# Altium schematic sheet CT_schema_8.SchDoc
size 254 x 194 mm
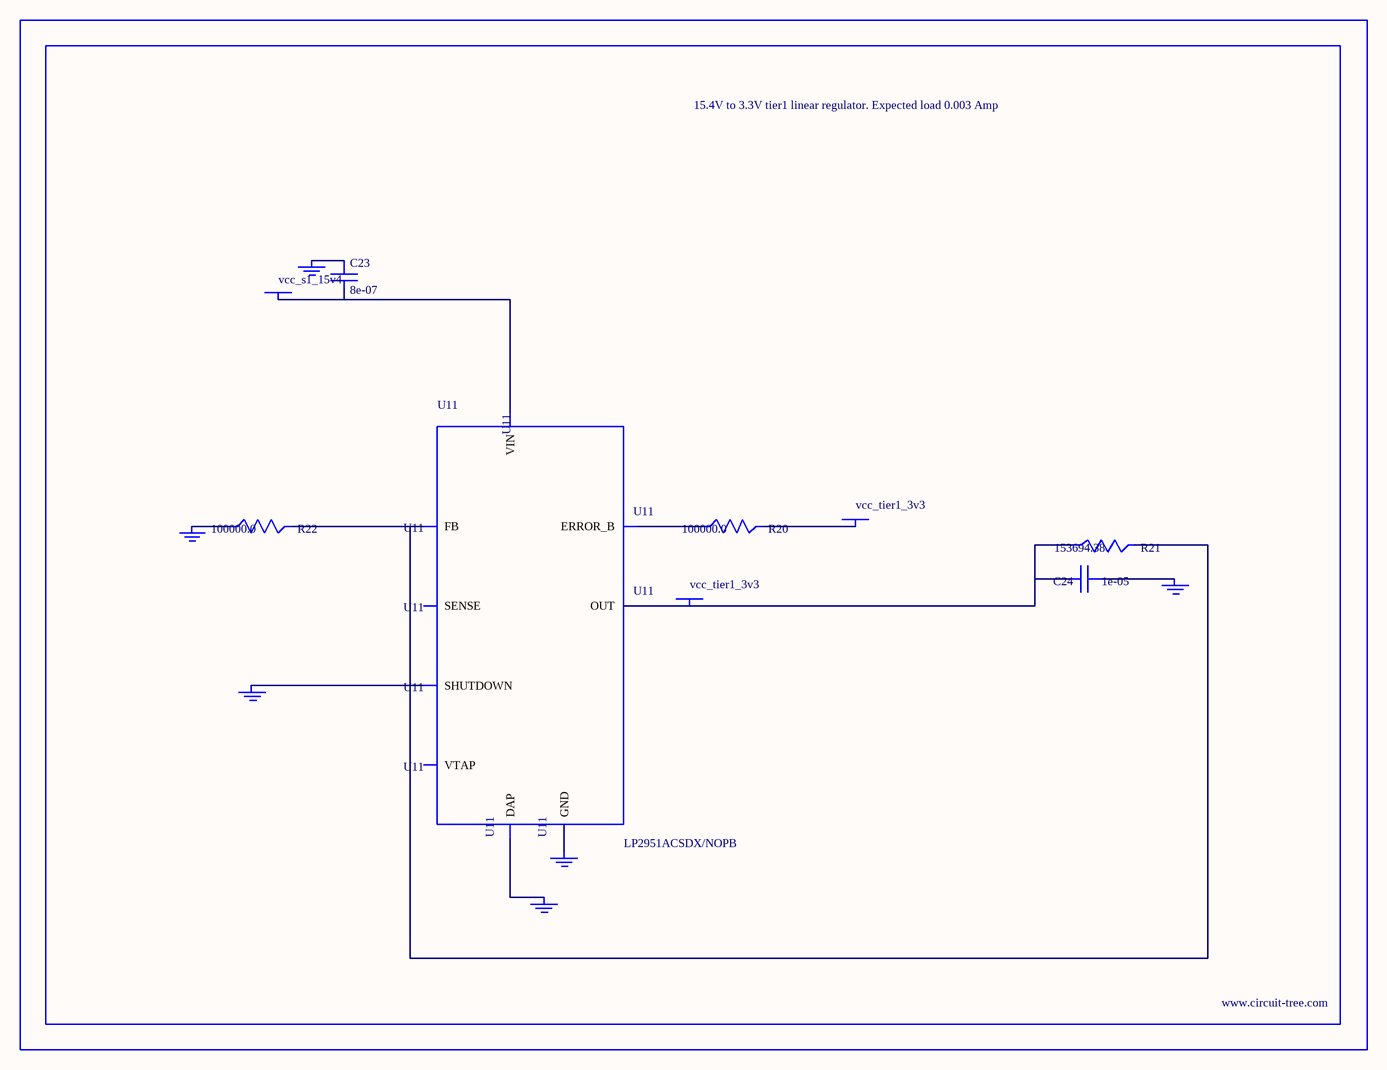
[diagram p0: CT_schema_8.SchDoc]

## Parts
BORDER7  (no value)
C23  8e-07  [R0603]
C24  1e-05  [C1210]
GND_INSTANCE_7_0  (no value)
GND_INSTANCE_7_1  (no value)
GND_INSTANCE_7_2  (no value)
GND_INSTANCE_7_3  (no value)
GND_INSTANCE_7_4  (no value)
GND_INSTANCE_7_5  (no value)
POWER_INSTANCE_7_0  vcc_tier1_3v3
POWER_INSTANCE_7_1  vcc_s1_15v4
POWER_INSTANCE_7_2  vcc_tier1_3v3
R20  100000.0  [R0603]
R21  153694.38  [R0603]
R22  100000.0  [R0603]
U11  LP2951ACSDX/NOPB  [WSON-8]

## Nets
NetC23_1: C23.1 GND_INSTANCE_7_3.0(GND)
NetC23_2: C23.2 POWER_INSTANCE_7_1.0(PWR) U11.8(VIN)
NetC24_1: C24.1 GND_INSTANCE_7_0.0(GND)
NetC24_2: C24.2 POWER_INSTANCE_7_2.0(PWR) R21.1 U11.1(OUT)
NetGND_INSTANCE_7_1_0: GND_INSTANCE_7_1.0(GND) U11.3(SHUTDOWN)
NetGND_INSTANCE_7_2_0: GND_INSTANCE_7_2.0(GND) R22.1
NetGND_INSTANCE_7_4_0: GND_INSTANCE_7_4.0(GND) U11.PAD(DAP)
NetGND_INSTANCE_7_5_0: GND_INSTANCE_7_5.0(GND) U11.4(GND)
NetPOWER_INSTANCE_7_0_0: POWER_INSTANCE_7_0.0(PWR) R20.2
NetR20_1: R20.1 U11.5(ERROR_B)
NetR21_2: R21.2 R22.2 U11.7(FB)

Not connected (* = marked no-connect by the designer): U11 2(SENSE) 6(VTAP)

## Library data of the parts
BORDER7 = BORDER_PAGE7
C23 = C23
C24 = GRM32DR61E106MA12L
GND_INSTANCE_7_0-GND_INSTANCE_7_5 = GND
POWER_INSTANCE_7_0-POWER_INSTANCE_7_2 = PWR
R20 R22 = RC0603JR-07100KL
R21 = R21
